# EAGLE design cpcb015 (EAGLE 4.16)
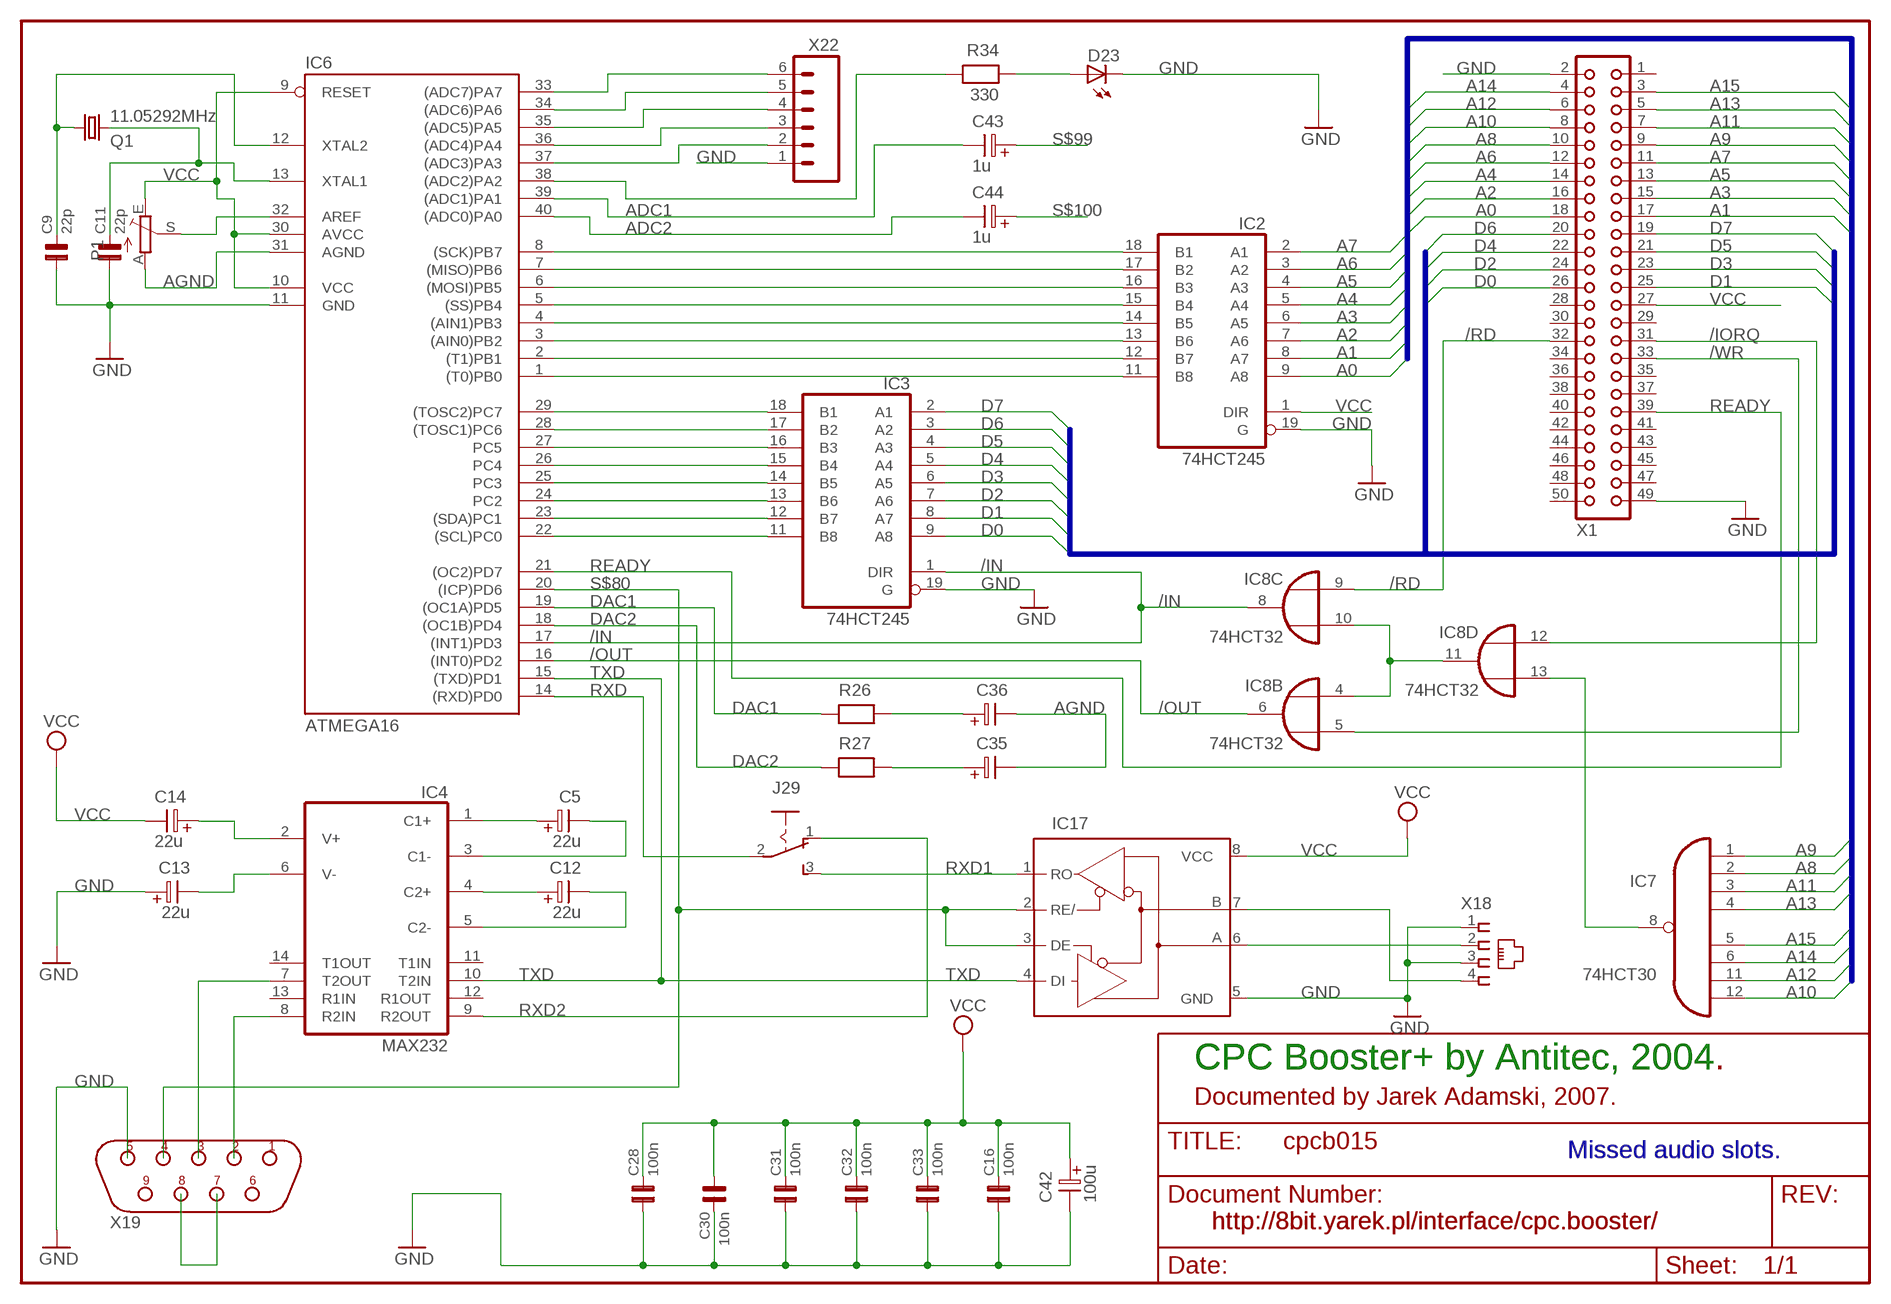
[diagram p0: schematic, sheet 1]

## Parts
C5  22u  ELC-2,5  [ES-2,5]
C9  22p  C2,5  [C2,5]
C11  22p  C2,5  [C2,5]
C12  22u  ELC-2,5  [ES-2,5]
C13  22u  ELC-2,5  [ES-2,5]
C14  22u  ELC-2,5  [ES-2,5]
C16  100n  C3,5  [C3,5]
C28  100n  C3,5  [C3,5]
C30  100n  C3,5  [C3,5]
C31  100n  C3,5  [C3,5]
C32  100n  C3,5  [C3,5]
C33  100n  C3,5  [C3,5]
C35  ELC-2,5  [ES-2,5]
C36  ELC-2,5  [ES-2,5]
C42  100u  ELC-2,5  [ES-2,5]
C43  1u  ELC-2,5  [ES-2,5]
C44  1u  ELC-2,5  [ES-2,5]
D23  LEDSQR2X5  [LED2X5]
IC2  74HCT245  74ACT245N  [DIL20]
IC3  74HCT245  74ACT245N  [DIL20]
IC4  MAX232  [DIL16]
IC6  ATMEGA16  MEGA163P  [DIL40]
IC7  74HCT30  74HCT30N  [DIL14]
IC8  74HCT32  74HCT32N  [DIL14]
IC17  MAX3468CPA  [DIL08]
J29  M251  [M251]
P1  TRIM_EU-B25P  [B25P]
Q1  11.05292MHz  CRYTALHC18U-V  [HC18U-V]
R26  RESEU-7,5  [R-7,5]
R27  RESEU-7,5  [R-7,5]
R34  330  RESEU-5  [R-5]
X1  CON50  [CON50]
X18  215876-6  [215876-6]
X19  DB9M/90  [D-09M/90]
X22  M06  [06P]

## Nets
/IN: IC3.1(DIR) IC6.17((INT1)PD3) IC8.8(C:O)
/IORQ: IC8.12(D:I0) X1.31
/OUT: IC6.16((INT0)PD2) IC8.6(B:O)
/RD: IC8.9(C:I0) X1.32
/WR: IC8.5(B:I1) X1.33
A0: IC2.9(A8) X1.18
A1: IC2.8(A7) X1.17
A2: IC2.7(A6) X1.16
A3: IC2.6(A5) X1.15
A4: IC2.5(A4) X1.14
A5: IC2.4(A3) X1.13
A6: IC2.3(A2) X1.12
A7: IC2.2(A1) X1.11
A8: IC7.2(I1) X1.10
A9: IC7.1(I0) X1.9
A10: IC7.12(I7) X1.8
A11: IC7.3(I2) X1.7
A12: IC7.11(I6) X1.6
A13: IC7.4(I3) X1.5
A14: IC7.6(I5) X1.4
A15: IC7.5(I4) X1.3
ADC1: C43.2 IC6.39((ADC1)PA1)
ADC2: C44.2 IC6.40((ADC0)PA0)
AGND: C35.2 C36.2 IC6.31(AGND) P1.A
AREF: IC6.32(AREF) P1.S
D0: IC3.9(A8) X1.26
D1: IC3.8(A7) X1.25
D2: IC3.7(A6) X1.24
D3: IC3.6(A5) X1.23
D4: IC3.5(A4) X1.22
D5: IC3.4(A3) X1.21
D6: IC3.3(A2) X1.20
D7: IC3.2(A1) X1.19
DAC1: IC6.19((OC1A)PD5) R26.1
DAC2: IC6.18((OC1B)PD4) R27.1
GND: C9.1 C11.1 C13.1 C16.1 C28.1 C30.2 C31.1 C32.1 C33.1 C42.2 D23.K(C) IC2.19(G) IC3.19(G) IC6.11(GND) IC17.5(GND) X1.2 X1.49 X18.1 X18.3 X19.5 X22.1
LED: IC6.38((ADC2)PA2) R34.2
READY: IC6.21((OC2)PD7) X1.39
RXD: IC6.14((RXD)PD0) J29.2(P)
RXD1: IC17.1(RO) J29.3(S)
RXD2: IC4.9(R2OUT) J29.1(O)
S$17: IC2.18(B1) IC6.8((SCK)PB7)
S$18: IC3.18(B1) IC6.29((TOSC2)PC7)
S$20: IC2.15(B4) IC6.5((SS)PB4)
S$22: IC2.13(B6) IC6.3((AIN0)PB2)
S$23: IC2.12(B7) IC6.2((T1)PB1)
S$24: IC2.11(B8) IC6.1((T0)PB0)
S$25: IC3.17(B2) IC6.28((TOSC1)PC6)
S$26: IC2.14(B5) IC6.4((AIN1)PB3)
S$27: IC2.16(B3) IC6.6((MOSI)PB5)
S$28: IC2.17(B2) IC6.7((MISO)PB6)
S$29: IC3.16(B3) IC6.27(PC5)
S$30: IC3.15(B4) IC6.26(PC4)
S$31: IC3.14(B5) IC6.25(PC3)
S$32: IC3.13(B6) IC6.24(PC2)
S$33: IC3.12(B7) IC6.23((SDA)PC1)
S$34: IC3.11(B8) IC6.22((SCL)PC0)
S$43: IC17.6(A) X18.2
S$44: IC7.8(O) IC8.13(D:I1)
S$46: IC8.4(B:I0) IC8.10(C:I1) IC8.11(D:O)
S$49: IC17.7(B) X18.4
S$53: C9.2 IC6.12(XTAL2) Q1.1
S$54: C11.2 IC6.13(XTAL1) Q1.2
S$55: X19.7 X19.8
S$57: C5.1 IC4.1(C1+)
S$59: C5.2 IC4.3(C1-)
S$62: IC6.36((ADC4)PA4) X22.3
S$63: IC6.35((ADC5)PA5) X22.4
S$65: C12.1 IC4.4(C2+)
S$73: C12.2 IC4.5(C2-)
S$75: C13.2 IC4.6(V-)
S$78: IC4.7(T2OUT) X19.3
S$79: C14.1 IC4.2(V+)
S$80: IC6.20((ICP)PD6) IC17.2(RE/) IC17.3(DE) X19.4
S$81: D23.A R34.1
S$84: IC4.8(R2IN) X19.2
S$88: IC6.37((ADC3)PA3) X22.2
S$90: IC6.34((ADC6)PA6) X22.5
S$91: IC6.33((ADC7)PA7) X22.6
S$97: C36.1 R26.2
S$98: C35.1 R27.2
S$99: C43.1
S$100: C44.1
TXD: IC4.10(T2IN) IC6.15((TXD)PD1) IC17.4(DI)
VCC: C14.2 C16.2 C28.2 C30.1 C31.2 C32.2 C33.2 C42.1 IC2.1(DIR) IC6.9(RESET) IC6.10(VCC) IC6.30(AVCC) IC17.8(VCC) P1.E X1.27
Unconnected: IC4.11(T1IN) IC4.12(R1OUT) IC4.13(R1IN) IC4.14(T1OUT) IC8.1(A:I0) IC8.2(A:I1) IC8.3(A:O) X1.1 X1.28 X1.29 X1.30 X1.34 X1.35 X1.36 X1.37 X1.38 X1.40 X1.41 X1.42 X1.43 X1.44 X1.45 X1.46 X1.47 X1.48 X1.50 X19.1 X19.6 X19.9

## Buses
A[0..15]
D[0..7]

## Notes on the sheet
- CPC Booster+ by Antitec, 2004 | CPC Booster+ by Antitec, 2004.
- Documented by Jarek Adamski, 2007.
- Missed audio slots. | Missed audio slots.
- http://8bit.yarek.pl/interface/cpc.booster/ | http://8bit.yarek.pl/interface/cpc.booster/

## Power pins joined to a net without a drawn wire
GND: IC2.10(GND) IC3.10(GND) IC4.15(GND) IC7.7(GND) IC8.7(P:GND)
VCC: IC2.20(VCC) IC3.20(VCC) IC4.16(VCC) IC7.14(VCC) IC8.14(P:VCC)

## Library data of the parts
C5 C12-C14 C35 C36 C42-C44 = discrete:ELC-2,5
C9 C11 = cap-pan:C2,5
C16 C28 C30-C33 = cap-pan:C3,5
D23 = led:LED: LED
IC2 IC3 = atmel:74*245: Octal BUS TRANSCEIVER, 3-state
IC4 = maxim:MAX232: RS232 TRANSEIVER
IC6 = atmel:MEGA163*P: MICROCONTROLLER 16 Kbytes FLASH 1 Kbytes EEPROM 1 Kbytes SRAM UART 8-channel 10 bit ADC hardware multiplier Source: avr.lbr
IC7 = 74xx-eu:74*30: 8-input NAND gate
IC8 = 74xx-eu:74*32: Quad 2-input OR gate
IC17 = maxim:MAX34*: +5V, Fail-Safe, 40Mbps, Profibus RS-485/RS-422 Transceivers Source: MAX3465-MAX3469.pdf
J29 = switch:M251: SLIDING SWITCH Mors, distributor Buerklin, 11G702
P1 = pot:TRIM_EU-: POTENTIOMETER
Q1 = crystal:CRYTAL: CRYSTAL
R26 R27 = discrete:RESEU-7,5
R34 = discrete:RESEU-5
X1 = con-harting:CON50: CONNECTOR
X18 = con-amp:215876-6: AMP connector
X19 = connect:DB9M/90
X22 = con-amp-quick:M06: AMP QUICK CONNECTOR

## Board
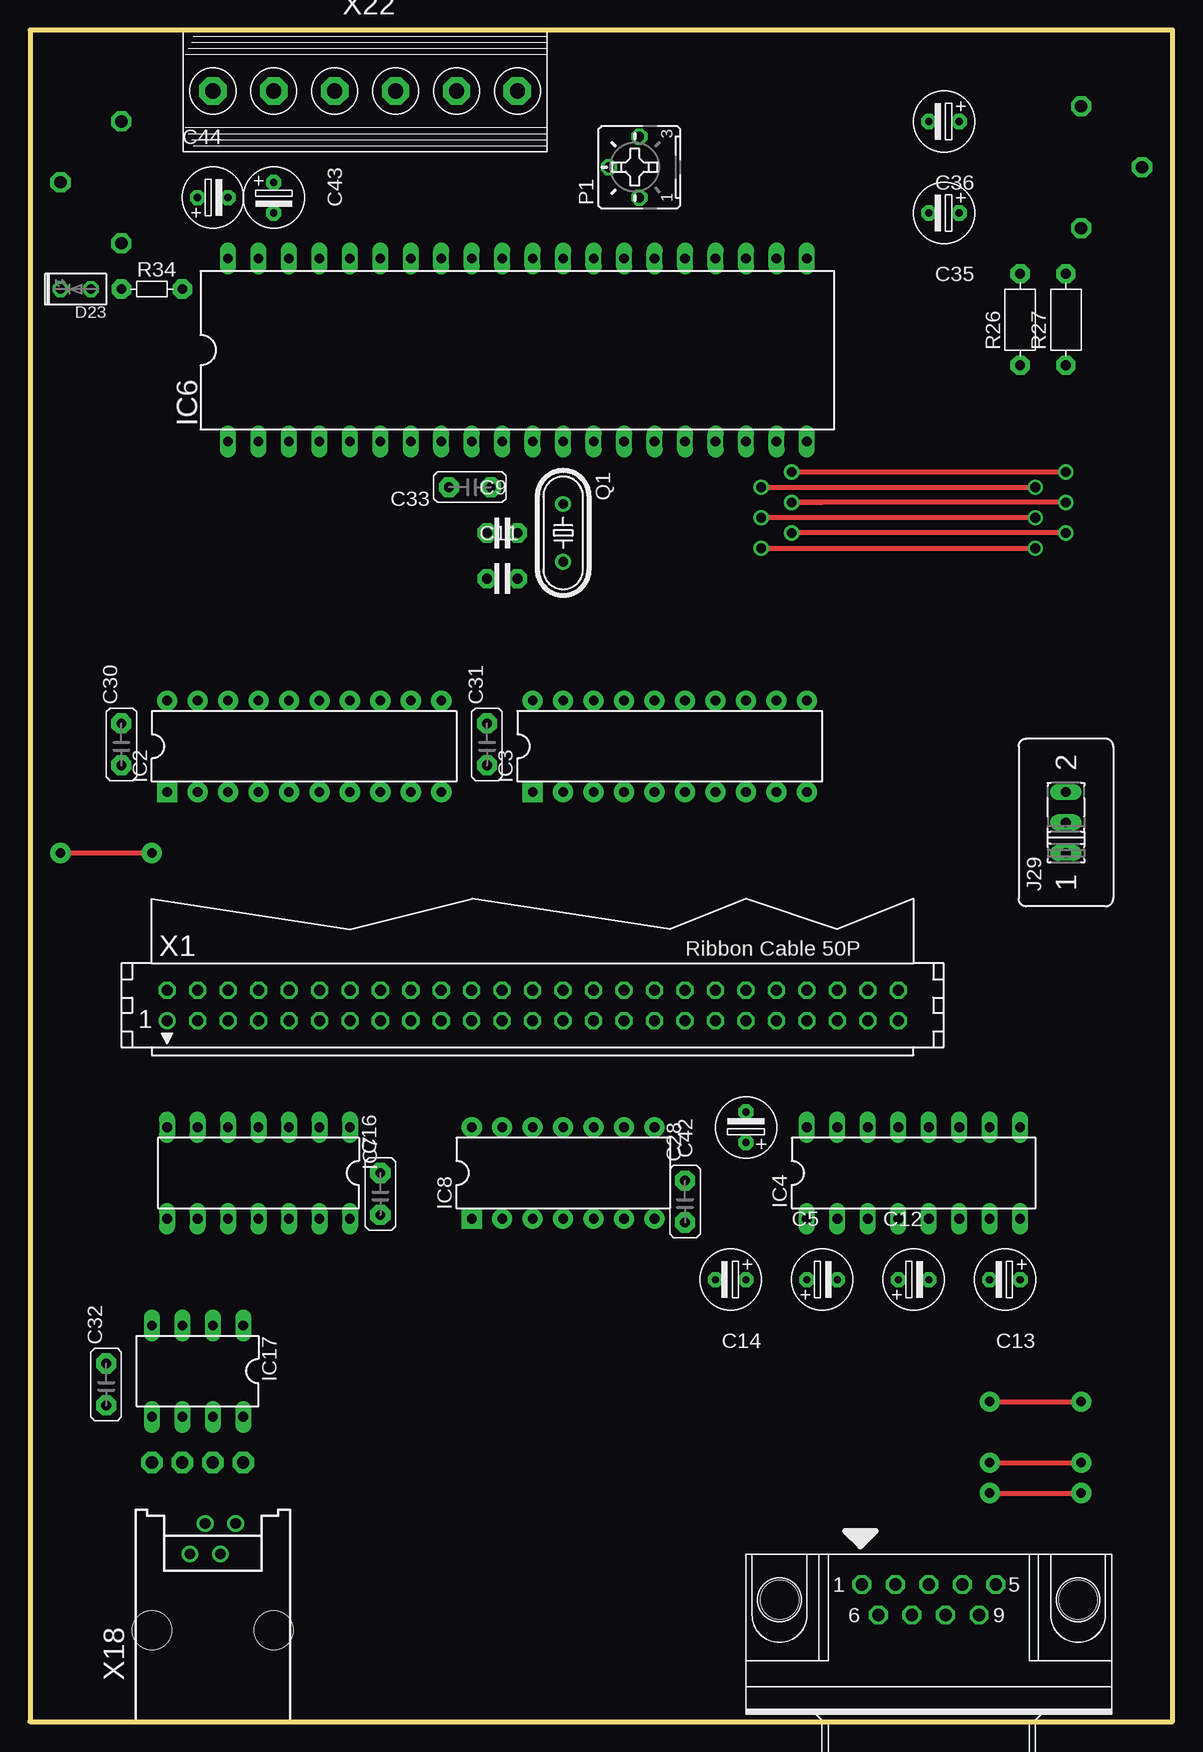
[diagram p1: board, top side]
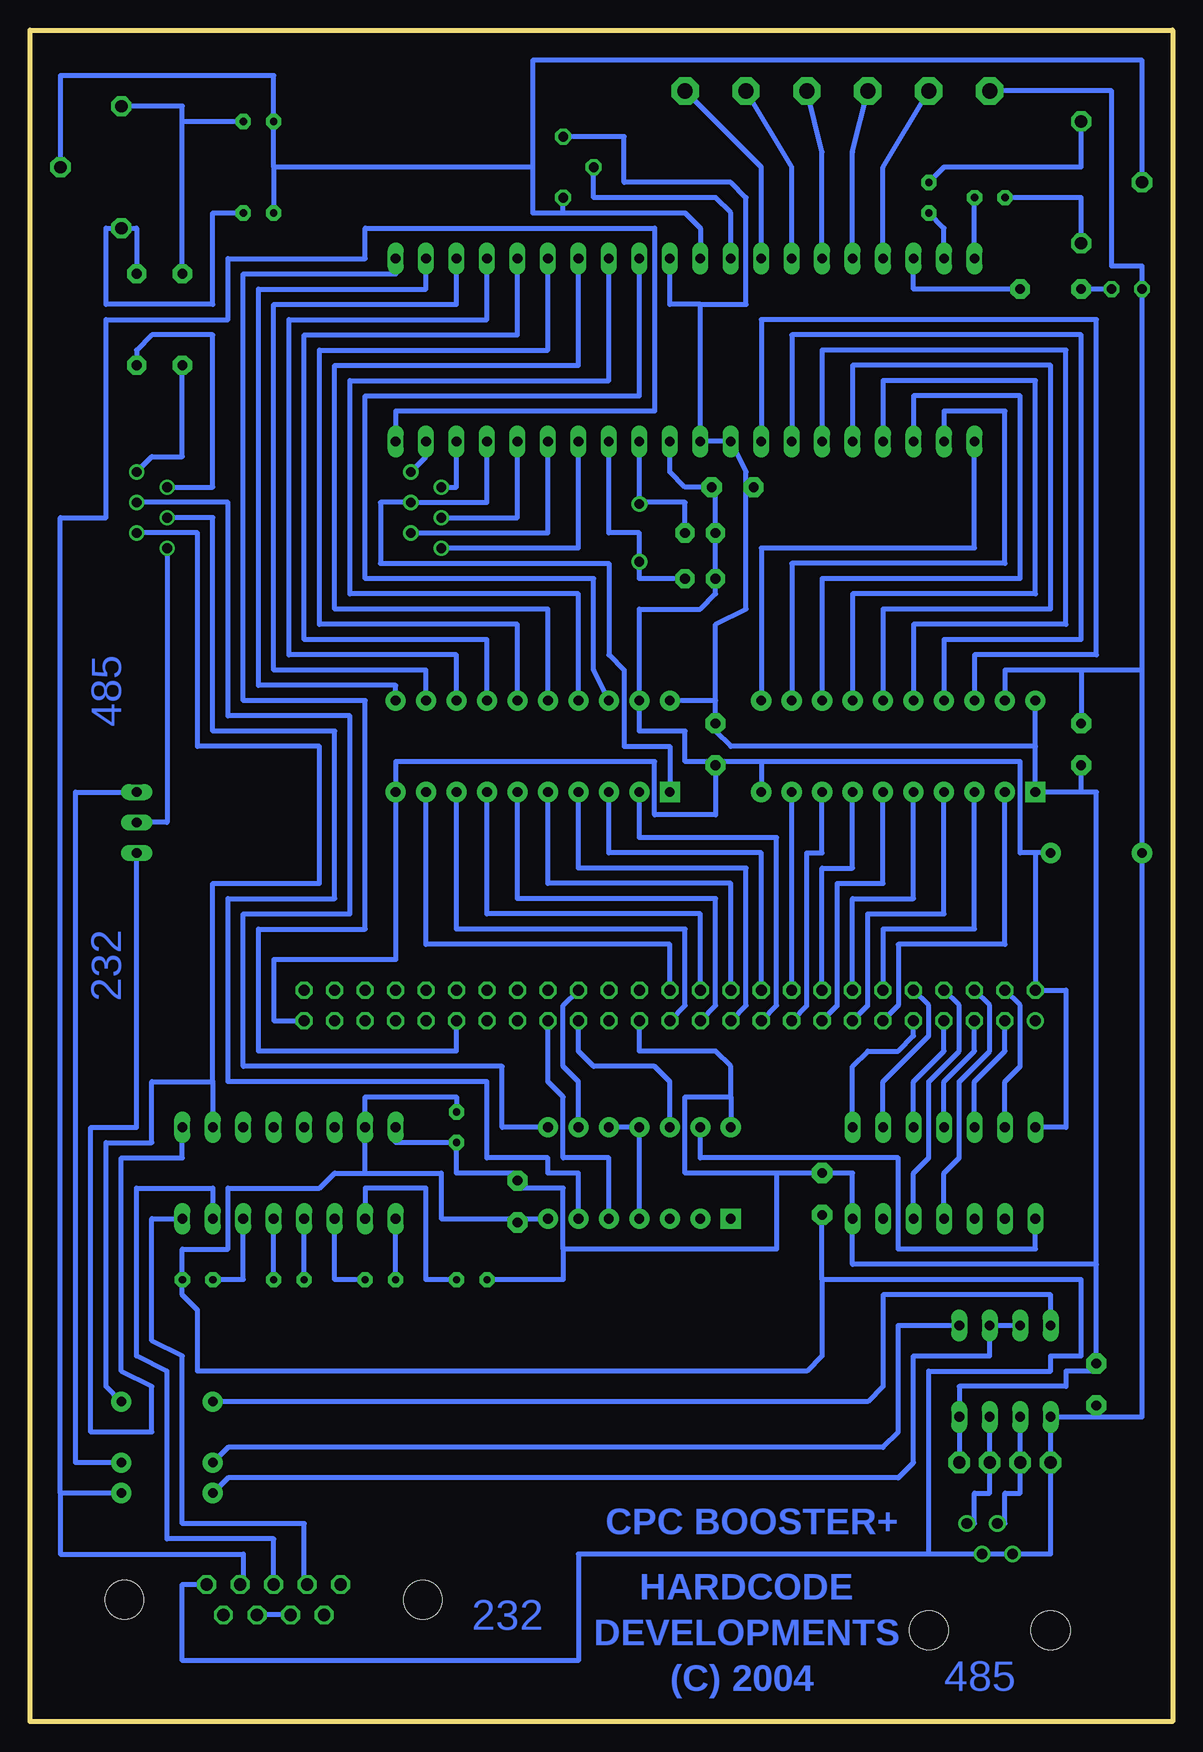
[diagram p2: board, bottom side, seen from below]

Size 95.25 x 140.97 mm. Coordinates in mm from the lower left corner, seen from the top.
Outline: 0,140.97 0,0 95.25,0 95.25,140.97 0,140.97
Copper layers (1*16): Top 0.035mm / dielectric 1.5mm / Bottom 0.035mm
Design rules "default": minimum track width 10mil, minimum drill 24mil, track to track 8mil, track to pad 8mil, pad to pad 8mil, via to via 8mil, smd to smd 8mil, copper to edge 40mil, drill to drill 8mil, minimum pad ring 10mil, minimum via ring 8mil, stop-mask expansion 4mil, vias tented up to drill 0mil, thermal gap 10mil

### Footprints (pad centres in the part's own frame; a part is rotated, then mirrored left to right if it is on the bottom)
ES-2,5L = drill 0.61 pad 1.27 octagon: 1 0,0; 2 2.54,0
C-2,5 = drill 0.813 pad 1.6 octagon: 1 -1.27,0; 2 1.27,0
C3,5 = drill 0.813 pad 1.676 octagon: 1 -1.587,0; 2 1.905,0
LED2X5 = drill 0.813 octagon: A -1.27,0; K 1.27,0
DIL20 = drill 0.813 pad 1.676 square: 1 -11.43,-3.81 | drill 0.813 pad 1.676 round: 2 -8.89,-3.81; 3 -6.35,-3.81; 4 -3.81,-3.81; 5 -1.27,-3.81; 6 1.27,-3.81; 7 3.81,-3.81; 8 6.35,-3.81; 9 8.89,-3.81; 10 11.43,-3.81; 11 11.43,3.81; 12 8.89,3.81; 13 6.35,3.81; 14 3.81,3.81; 15 1.27,3.81; 16 -1.27,3.81; 17 -3.81,3.81; 18 -6.35,3.81; 19 -8.89,3.81; 20 -11.43,3.81
DIL-16 = drill 0.813 long: 1 -8.89,-3.81; 2 -6.35,-3.81; 3 -3.81,-3.81; 4 -1.27,-3.81; 5 1.27,-3.81; 6 3.81,-3.81; 7 6.35,-3.81; 8 8.89,-3.81; 9 8.89,3.81; 10 6.35,3.81; 11 3.81,3.81; 12 1.27,3.81; 13 -1.27,3.81; 14 -3.81,3.81; 15 -6.35,3.81; 16 -8.89,3.81
DIL40 = drill 0.813 long: 1 -24.13,-7.62; 2 -21.59,-7.62; 3 -19.05,-7.62; 4 -16.51,-7.62; 5 -13.97,-7.62; 6 -11.43,-7.62; 7 -8.89,-7.62; 8 -6.35,-7.62; 9 -3.81,-7.62; 10 -1.27,-7.62; 11 1.27,-7.62; 12 3.81,-7.62; 13 6.35,-7.62; 14 8.89,-7.62; 15 11.43,-7.62; 16 13.97,-7.62; 17 16.51,-7.62; 18 19.05,-7.62; 19 21.59,-7.62; 20 24.13,-7.62; 21 24.13,7.62; 22 21.59,7.62; 23 19.05,7.62; 24 16.51,7.62; 25 13.97,7.62; 26 11.43,7.62; 27 8.89,7.62; 28 6.35,7.62; 29 3.81,7.62; 30 1.27,7.62; 31 -1.27,7.62; 32 -3.81,7.62; 33 -6.35,7.62; 34 -8.89,7.62; 35 -11.43,7.62; 36 -13.97,7.62; 37 -16.51,7.62; 38 -19.05,7.62; 39 -21.59,7.62; 40 -24.13,7.62
DIL-14 = drill 0.813 long: 1 -7.62,-3.81; 2 -5.08,-3.81; 3 -2.54,-3.81; 4 0,-3.81; 5 2.54,-3.81; 6 5.08,-3.81; 7 7.62,-3.81; 8 7.62,3.81; 9 5.08,3.81; 10 2.54,3.81; 11 0,3.81; 12 -2.54,3.81; 13 -5.08,3.81; 14 -7.62,3.81
DIL14 = drill 0.813 pad 1.676 square: 1 -7.62,-3.81 | drill 0.813 pad 1.676 round: 2 -5.08,-3.81; 3 -2.54,-3.81; 4 0,-3.81; 5 2.54,-3.81; 6 5.08,-3.81; 7 7.62,-3.81; 8 7.62,3.81; 9 5.08,3.81; 10 2.54,3.81; 11 0,3.81; 12 -2.54,3.81; 13 -5.08,3.81; 14 -7.62,3.81
DIL-08 = drill 0.813 long: 1 -3.81,-3.81; 2 -1.27,-3.81; 3 1.27,-3.81; 4 3.81,-3.81; 5 3.81,3.81; 6 1.27,3.81; 7 -1.27,3.81; 8 -3.81,3.81
M251 = drill 0.813 long: 1 -2.54,0; 2 0,0; 3 2.54,0
B25P = drill 0.813 octagon: A -2.54,0; E 2.54,0; S 0,2.54
HC49/S = drill 0.813 round: 1 -2.413,0; 2 2.413,0
R-7,5 = drill 0.813 pad 1.6 octagon: 1 -3.81,0; 2 3.81,0
R-5 = drill 0.813 pad 1.6 octagon: 1 -2.54,0; 2 2.54,0
CON50 = drill 0.914 round: 1 -30.48,-1.27 | drill 0.914 octagon: 2 -30.48,1.27; 3 -27.94,-1.27; 4 -27.94,1.27; 5 -25.4,-1.27; 6 -25.4,1.27; 7 -22.86,-1.27; 8 -22.86,1.27; 9 -20.32,-1.27; 10 -20.32,1.27; 11 -17.78,-1.27; 12 -17.78,1.27; 13 -15.24,-1.27; 14 -15.24,1.27; 15 -12.7,-1.27; 16 -12.7,1.27; 17 -10.16,-1.27; 18 -10.16,1.27; 19 -7.62,-1.27; 20 -7.62,1.27; 21 -5.08,-1.27; 22 -5.08,1.27; 23 -2.54,-1.27; 24 -2.54,1.27; 25 0,-1.27; 26 0,1.27; 27 2.54,-1.27; 28 2.54,1.27; 29 5.08,-1.27; 30 5.08,1.27; 31 7.62,-1.27; 32 7.62,1.27; 33 10.16,-1.27; 34 10.16,1.27; 35 12.7,-1.27; 36 12.7,1.27; 37 15.24,-1.27; 38 15.24,1.27; 39 17.78,-1.27; 40 17.78,1.27; 41 20.32,-1.27; 42 20.32,1.27; 43 22.86,-1.27; 44 22.86,1.27; 45 25.4,-1.27; 46 25.4,1.27; 47 27.94,-1.27; 48 27.94,1.27; 49 30.48,-1.27; 50 30.48,1.27
215876-6 = drill 0.889 round: 1 -1.905,6.35; 2 -0.635,8.89; 3 0.635,6.35; 4 1.905,8.89 | hole 3.251: -5.08,0; 5.08,0
D-09M/90 = drill 1.016 pad 1.575 octagon: 1 5.588,-1.27; 2 2.794,-1.27; 3 0,-1.27; 4 -2.794,-1.27; 5 -5.588,-1.27; 6 4.191,1.27; 7 1.397,1.27; 8 -1.397,1.27; 9 -4.191,1.27 | hole 3.2: 12.446,0; -12.446,0
CLAMP-06 = drill 1.27 pad 2.286 octagon: 1 -12.7,0; 2 -7.62,0; 3 -2.54,0; 4 2.54,0; 5 7.62,0; 6 12.7,0

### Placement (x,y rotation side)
C5  22u  [ES-2,5L]  64.77,36.83 0 top
C9  22p  [C-2,5]  39.37,99.06 0 top
C11  22p  [C-2,5]  39.37,95.25 0 top
C12  22u  [ES-2,5L]  72.39,36.83 0 top
C13  22u  [ES-2,5L]  82.55,36.83 180 top
C14  22u  [ES-2,5L]  59.69,36.83 180 top
C16  29.21,43.81 90 top
C28  54.61,43.18 90 top
C30  7.62,81.28 90 top
C31  38.1,81.28 90 top
C32  6.35,27.94 90 top
C33  36.83,102.87 180 top
C35  [ES-2,5L]  77.47,125.73 180 top
C36  [ES-2,5L]  77.47,133.35 180 top
C42  100u  [ES-2,5L]  59.69,48.26 90 top
C43  1u  [ES-2,5L]  20.32,128.27 270 top
C44  1u  [ES-2,5L]  13.97,127 0 top
D23  3.81,119.38 180 top
IC2  22.86,81.28 0 top
IC3  53.34,81.28 0 top
IC4  MAX232  [DIL-16]  73.66,45.72 0 top
IC6  40.64,114.3 0 top
IC7  74HCT30  [DIL-14]  19.05,45.72 180 top
IC8  44.45,45.72 0 top
IC17  [DIL-08]  13.97,29.21 180 top
J29  86.36,74.93 90 top
P1  50.8,129.54 90 top
Q1  11.05292MHz  [HC49/S]  44.45,99.06 270 top
R26  82.55,116.84 90 top
R27  86.36,116.84 90 top
R34  10.16,119.38 0 top
X1  41.91,59.69 0 top
X18  15.24,7.62 0 top
X19  74.93,10.16 180 top
X22  [CLAMP-06]  27.94,135.89 0 top

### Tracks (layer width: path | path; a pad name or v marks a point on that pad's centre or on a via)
/IN  (via drill 0.81 pad 1.27)
  Top 0.406: 66.04,101.6 v63.5,101.6 v86.36,101.6
  Bottom 0.406: IC8.8 55.88,49.53 55.88,54.61 77.47,54.61 77.47,67.31 68.58,67.31 68.58,83.82 78.74,83.82 78.74,101.6 v86.36,101.6 | IC3.1 41.91,81.28 45.72,81.28 45.72,87.63 46.99,88.9 46.99,96.52 66.04,96.52 66.04,101.6 v63.5,101.6 57.15,101.6 IC6.17
/IORQ
  Bottom 0.406: IC8.12 41.91,53.34 43.18,54.61 48.26,54.61 49.53,55.88 X1.31
/OUT  (via drill 0.81 pad 1.27)
  Top 0.406: v83.82,100.33 v60.96,100.33
  Bottom 0.406: IC8.6 49.53,45.72 52.07,45.72 52.07,46.99 57.15,46.99 57.15,53.34 78.74,53.34 78.74,68.58 69.85,68.58 69.85,82.55 80.01,82.55 80.01,100.33 v83.82,100.33 | IC6.16 54.61,100.33 v60.96,100.33
/RD
  Bottom 0.406: X1.32 50.8,59.69 50.8,54.61 49.53,53.34 IC8.9
/WR
  Bottom 0.406: X1.33 52.07,53.34 50.8,52.07 50.8,46.99 46.99,46.99 IC8.5
A0
  Bottom 0.406: X1.18 IC2.9
A1
  Bottom 0.406: X1.17 30.48,59.69 30.48,72.39 29.21,72.39 IC2.8
A2
  Bottom 0.406: X1.16 29.21,71.12 26.67,71.12 IC2.7
A3
  Bottom 0.406: X1.15 27.94,59.69 27.94,69.85 24.13,69.85 IC2.6
A4
  Bottom 0.406: X1.14 26.67,68.58 21.59,68.58 IC2.5
A5
  Bottom 0.406: X1.13 25.4,59.69 25.4,67.31 19.05,67.31 IC2.4
A6
  Bottom 0.406: X1.12 24.13,66.04 16.51,66.04 IC2.3
A7
  Bottom 0.406: X1.11 22.86,59.69 22.86,64.77 13.97,64.77 IC2.2
A8
  Bottom 0.406: X1.10 20.32,59.69 20.32,57.15 24.13,53.34 IC7.2
A9
  Bottom 0.406: IC7.1 26.67,54.61 25.4,55.88 22.86,55.88 21.59,57.15 X1.9
A10
  Bottom 0.406: X1.8 17.78,59.69 17.78,55.88 20.32,53.34 20.32,46.99 21.59,45.72 IC7.12
A11
  Bottom 0.406: IC7.3 21.59,53.34 19.05,55.88 X1.7
A12
  Bottom 0.406: X1.6 15.24,59.69 15.24,55.88 17.78,53.34 17.78,46.99 19.05,45.72 IC7.11
A13
  Bottom 0.406: IC7.4 19.05,53.34 16.51,55.88 X1.5
A14
  Bottom 0.406: IC7.6 13.97,53.34 12.7,54.61 12.7,59.69 X1.4
A15
  Bottom 0.406: X1.3 13.97,55.88 16.51,53.34 IC7.5
ADC1
  Bottom 0.406: IC6.39 19.05,124.46 C43.2
ADC2
  Bottom 0.406: IC6.40 C44.2
AGND  (via drill 1.02 pad 1.68)
  Bottom 0.406: 74.93,129.54 C35.2 | 74.93,129.54 C36.2 74.93,137.16 92.71,137.16 v92.71,129.54 | 53.34,129.54 74.93,129.54 | IC6.31 39.37,124.46 40.64,125.73 50.8,125.73 | 53.34,129.54 53.34,125.73 50.8,125.73 | 50.8,125.73 P1.A | 53.34,129.54 53.34,138.43 2.54,138.43 v2.54,128.27
AREF
  Bottom 0.406: IC6.32 36.83,125.73 38.1,127 48.26,127 P1.S
D0
  Bottom 0.406: X1.26 41.91,64.77 62.23,64.77 IC3.9
D1
  Bottom 0.406: X1.25 40.64,59.69 40.64,66.04 59.69,66.04 IC3.8
D2
  Bottom 0.406: X1.24 39.37,67.31 57.15,67.31 IC3.7
D3
  Bottom 0.406: X1.23 38.1,59.69 38.1,68.58 54.61,68.58 IC3.6
D4
  Bottom 0.406: X1.22 36.83,69.85 52.07,69.85 IC3.5
D5
  Bottom 0.406: X1.21 35.56,59.69 35.56,71.12 49.53,71.12 IC3.4
D6
  Bottom 0.406: X1.20 34.29,72.39 46.99,72.39 IC3.3
D7
  Bottom 0.406: X1.19 33.02,59.69 33.02,73.66 44.45,73.66 IC3.2
DAC1  (via drill 0.81 pad 1.27)
  Top 0.406: v63.5,104.14 v86.36,104.14
  Bottom 0.406: R26.1 82.55,105.41 85.09,105.41 v86.36,104.14 | IC6.19 62.23,105.41 v63.5,104.14
DAC2  (via drill 0.81 pad 1.27)
  Top 0.406: v60.96,102.87 v83.82,102.87
  Bottom 0.406: v83.82,102.87 80.01,102.87 80.01,115.57 85.09,115.57 86.36,114.3 R27.1 | IC6.18 59.69,102.87 v60.96,102.87
GND  (via drill 0.81 pad 1.68, 1.02 pad 1.78)
  Top 0.406: v2.54,72.39 v10.16,72.39
  Bottom 0.406: C42.2 59.69,52.07 67.31,52.07 IC4.15 67.31,45.72 | 67.31,45.72 60.96,45.72 60.96,41.91 54.93,41.91 C28.1 54.61,41.91 IC8.7 | 67.31,45.72 69.85,45.72 71.12,44.45 78.74,44.45 78.74,39.37 82.55,39.37 C13.1 82.55,35.56 81.28,34.29 81.28,29.21 30.48,29.21 29.21,30.48 29.21,36.83 | IC6.11 41.91,104.14 40.64,102.87 C33.1 38.1,102.87 C9.1 C11.1 38.1,93.98 39.37,92.71 44.45,92.71 IC3.19 44.45,82.55 40.64,82.55 40.64,80.01 38.1,80.01 | 6.35,25.4 C32.1 6.35,26.67 | 6.35,25.4 IC17.5 v10.16,21.59 10.16,13.97 X18.1 X18.3 20.32,13.97 | 6.35,25.4 2.54,25.4 v2.54,72.39 2.54,87.63 | X19.5 82.55,11.43 82.55,5.08 49.53,5.08 49.53,13.97 20.32,13.97 | X22.1 5.08,135.89 5.08,121.29 2.54,121.29 D23.K 2.54,87.63 | IC2.19 13.97,87.63 7.62,87.63 | X1.49 74.93,58.42 74.93,63.5 64.77,63.5 IC3.10 64.77,80.01 43.18,80.01 43.18,75.56 38.1,75.56 C31.1 38.1,80.01 | 29.21,36.83 7.62,36.83 7.62,30.48 10.16,30.48 10.16,29.21 20.32,29.21 20.32,13.97 | 29.21,36.83 C16.1 | 2.54,87.63 7.62,87.63 | 7.62,87.63 C30.2 | 11.43,72.39 X1.2 8.89,60.96 8.89,49.53 IC7.7 | 11.43,72.39 12.7,72.39 12.7,80.01 34.29,80.01 | 34.29,80.01 IC2.10 | 34.29,80.01 38.1,80.01 | v10.16,72.39 11.43,72.39
LED
  Bottom 0.406: R34.2 21.59,119.38 IC6.38
READY
  Bottom 0.406: IC6.21 64.77,120.65 77.47,120.65 77.47,85.09 67.31,85.09 67.31,66.04 76.2,66.04 76.2,55.88 59.69,55.88 X1.39
RXD  (via drill 0.81 pad 1.27)
  Top 0.406: v60.96,97.79 v83.82,97.79
  Bottom 0.406: IC6.14 49.53,97.79 v60.96,97.79 | v83.82,97.79 83.82,74.93 J29.2
RXD1  (via drill 0.81 pad 1.68)
  Top 0.406: v80.01,21.59 v87.63,21.59
  Bottom 0.406: J29.3 91.44,77.47 91.44,21.59 v87.63,21.59 | IC17.1 22.86,33.02 22.86,24.13 24.13,22.86 78.74,22.86 v80.01,21.59
RXD2
  Bottom 0.406: J29.1 86.36,49.53 90.17,49.53 90.17,24.13 85.09,24.13 85.09,27.94 87.63,29.21 87.63,46.99 82.55,46.99 IC4.9
S$17
  Bottom 0.406: IC2.18 16.51,88.9 6.35,88.9 6.35,116.84 34.29,116.84 IC6.8
S$18
  Bottom 0.406: IC6.29 44.45,110.49 67.31,110.49 67.31,95.25 48.26,95.25 48.26,87.63 IC3.18
S$20
  Bottom 0.406: IC2.15 24.13,92.71 10.16,92.71 10.16,113.03 26.67,113.03 IC6.5
S$22
  Bottom 0.406: IC2.13 29.21,95.25 12.7,95.25 12.7,110.49 21.59,110.49 IC6.3
S$23
  Bottom 0.406: IC2.12 31.75,96.52 13.97,96.52 13.97,109.22 19.05,109.22 IC6.2
S$24
  Bottom 0.406: IC2.11 34.29,97.79 16.51,97.79 IC6.1
S$25
  Bottom 0.406: IC3.17 49.53,93.98 68.58,93.98 68.58,111.76 46.99,111.76 IC6.28
S$26
  Bottom 0.406: IC6.4 24.13,111.76 11.43,111.76 11.43,93.98 26.67,93.98 IC2.14
S$27
  Bottom 0.406: IC6.6 29.21,114.3 8.89,114.3 8.89,91.44 21.59,91.44 IC2.16
S$28
  Bottom 0.406: IC6.7 31.75,115.57 7.62,115.57 7.62,90.17 19.05,90.17 IC2.17
S$29
  Bottom 0.406: IC6.27 49.53,113.03 69.85,113.03 69.85,92.71 52.07,92.71 IC3.16
S$30
  Bottom 0.406: IC3.15 54.61,91.44 71.12,91.44 71.12,114.3 52.07,114.3 IC6.26
S$31
  Bottom 0.406: IC6.25 54.61,115.57 72.39,115.57 72.39,90.17 57.15,90.17 IC3.14
S$32
  Bottom 0.406: IC3.13 59.69,88.9 73.66,88.9 73.66,116.84 57.15,116.84 IC6.24
S$33
  Bottom 0.406: IC6.23 59.69,118.11 74.93,118.11 74.93,87.63 62.23,87.63 IC3.12
S$34
  Bottom 0.406: IC3.11 64.77,86.36 76.2,86.36 76.2,119.38 62.23,119.38 IC6.22
S$43  (via drill 1.02 pad 1.78)
  Bottom 0.406: IC17.6 v12.7,21.59 12.7,19.05 13.97,19.05 13.97,16.51 X18.2
S$44
  Bottom 0.406: IC8.13 39.37,46.99 22.86,46.99 22.86,39.37 11.43,39.37 IC7.8
S$46
  Bottom 0.406: IC8.10 IC8.11 IC8.4
S$49  (via drill 1.02 pad 1.78)
  Bottom 0.406: IC17.7 v15.24,21.59 15.24,19.05 16.51,19.05 16.51,16.51 X18.4
S$53
  Bottom 0.406: C9.2 40.64,101.6 44.45,101.6 | 44.45,101.6 IC6.12 | 44.45,101.6 Q1.1
S$54
  Bottom 0.406: C11.2 44.45,95.25 Q1.2 44.45,99.06 46.99,99.06 IC6.13
S$55
  Bottom 0.406: X19.7 X19.8
S$57
  Bottom 0.406: C5.1 IC4.1
S$59
  Bottom 0.406: C5.2 69.85,36.83 IC4.3
S$62
  Bottom 0.406: IC6.36 26.67,130.81 X22.3
S$63
  Bottom 0.406: IC6.35 29.21,130.81 X22.4
S$65
  Bottom 0.406: C12.1 IC4.4
S$73
  Bottom 0.406: C12.2 IC4.5
S$75
  Bottom 0.406: C13.2 77.47,36.83 IC4.6
S$78
  Bottom 0.406: IC4.7 80.01,44.45 86.36,44.45 86.36,30.48 83.82,29.21 83.82,15.24 74.93,15.24 X19.3
S$79
  Bottom 0.406: C14.1 62.23,36.83 62.23,44.45 67.31,44.45 IC4.2
S$80  (via drill 0.81 pad 1.68)
  Top 0.406: v80.01,19.05 v87.63,19.05
  Bottom 0.406: IC17.3 IC17.2 15.24,30.48 21.59,30.48 21.59,21.59 22.86,20.32 78.74,20.32 v80.01,19.05 | 92.71,19.05 92.71,100.33 88.9,100.33 88.9,116.84 78.74,116.84 78.74,121.92 67.31,121.92 67.31,124.46 43.18,124.46 43.18,109.22 64.77,109.22 IC6.20 | 92.71,19.05 92.71,13.97 77.47,13.97 77.47,11.43 X19.4 | v87.63,19.05 92.71,19.05
S$81
  Bottom 0.406: D23.A R34.1
S$84
  Bottom 0.406: IC4.8 85.09,41.91 85.09,31.75 82.55,30.48 82.55,16.51 72.39,16.51 72.39,11.43 X19.2 71.75,11.43
S$88
  Bottom 0.406: IC6.37 24.13,129.54 X22.2
S$90
  Bottom 0.406: IC6.34 31.75,129.54 X22.5
S$91
  Bottom 0.406: IC6.33 34.29,129.54 X22.6
S$97  (via drill 1.02 pad 1.68)
  Bottom 0.406: 82.55,133.35 82.55,134.62 v87.63,134.62 | 82.55,133.35 C36.1 | R26.2 82.55,133.35
S$98  (via drill 1.02 pad 1.68)
  Bottom 0.406: C35.1 80.01,125.73 80.01,118.11 88.9,118.11 88.9,124.46 v87.63,124.46 86.36,124.46 R27.2
S$99  (via drill 1.02 pad 1.68)
  Bottom 0.406: v7.62,133.35 7.62,129.54 19.05,129.54 C43.1
S$100  (via drill 1.02 pad 1.68)
  Bottom 0.406: v7.62,123.19 7.62,127 C44.1
TXD  (via drill 0.81 pad 1.27, 0.81 pad 1.68)
  Top 0.406: v86.36,99.06 v63.5,99.06 | v80.01,26.67 v87.63,26.67
  Bottom 0.406: v86.36,99.06 81.28,99.06 81.28,81.28 71.12,81.28 71.12,69.85 80.01,69.85 80.01,53.34 | 80.01,53.34 IC4.10 | v87.63,26.67 88.9,27.94 88.9,48.26 85.09,48.26 85.09,53.34 80.01,53.34 | IC6.15 52.07,99.06 v63.5,99.06 | v80.01,26.67 25.4,26.67 24.13,27.94 24.13,35.56 10.16,35.56 IC17.4
VCC  (via drill 1.02 pad 1.78)
  Top 0.406: C30.1 7.62,80.01
  Bottom 0.406: IC4.16 64.77,48.26 C42.1 59.69,45.72 54.61,45.72 C28.2 54.61,44.45 50.8,44.45 50.8,39.37 | P1.E 45.72,132.08 45.72,128.27 36.83,128.27 35.56,127 35.56,118.11 39.37,118.11 | IC6.30 41.91,118.11 39.37,118.11 | 39.37,118.11 IC6.10 IC6.9 35.56,104.14 35.56,102.87 | X1.27 44.45,55.88 38.1,55.88 36.83,54.61 36.83,52.07 | 35.56,102.87 35.56,92.71 38.1,91.44 38.1,85.09 | 36.83,52.07 IC8.14 | 38.1,85.09 IC3.20 | 38.1,85.09 38.1,83.82 C31.2 38.1,82.55 36.83,81.28 11.43,81.28 | 36.83,52.07 40.64,52.07 40.64,45.72 33.02,45.72 | 50.8,39.37 33.02,39.37 33.02,45.72 | 11.43,81.28 IC2.20 | 11.43,81.28 IC2.1 7.62,77.47 | 33.02,45.72 C16.2 26.67,45.72 IC7.14 26.67,38.1 6.35,38.1 | 7.62,77.47 6.35,77.47 6.35,38.1 | C14.2 50.8,36.83 50.8,39.37 | 6.35,38.1 C32.2 6.35,29.21 8.89,29.21 8.89,27.94 17.78,27.94 IC17.8 v17.78,21.59 | 35.56,102.87 C33.2 | 7.62,77.47 C30.1

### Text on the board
Bottom: 485 | 232 | CPC BOOSTER+ | HARDCODE | 232 | DEVELOPMENTS | 485 | (C) 2004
